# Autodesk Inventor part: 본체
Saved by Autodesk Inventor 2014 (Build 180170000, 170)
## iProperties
Created: 2026-03
Part Number: 본체
Material: 일반
Document SubType Name: Modeling
Designer: dg
Density: 1 g/cm^3
Appearance: 기본값
Author: dg
Author: jhkim
Creation Date: 2025-06-27
Sending System: Autodesk Inventor 2026
Preprocessor: ST-DEVELOPER v20.1
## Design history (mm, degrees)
node "본체1"
node "솔리드1"
node "기준1"
